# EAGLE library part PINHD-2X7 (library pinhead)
PIN HEADER
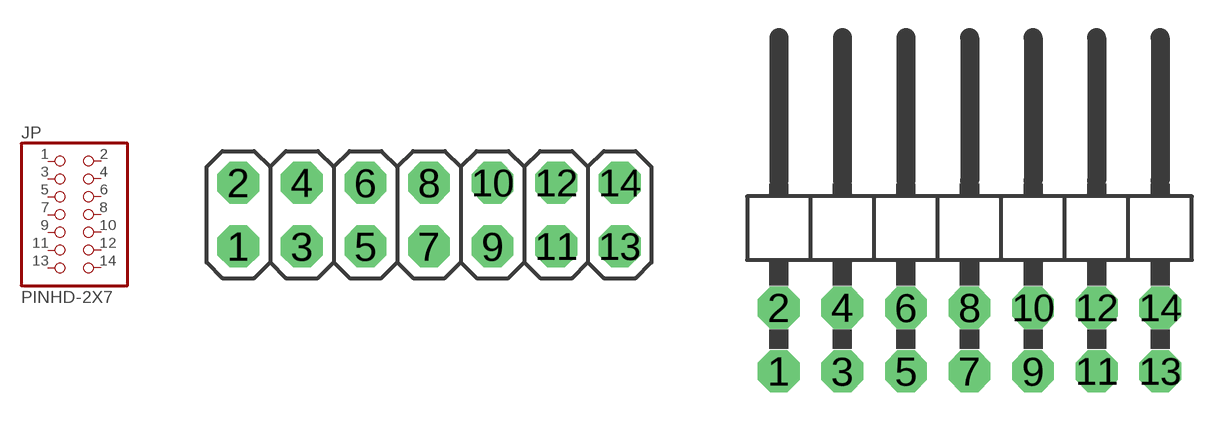
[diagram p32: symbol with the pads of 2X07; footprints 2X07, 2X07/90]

Designator prefix JP

## PINHD-2X7  [2X07]
1  1  pas
2  2  pas
3  3  pas
4  4  pas
5  5  pas
6  6  pas
7  7  pas
8  8  pas
9  9  pas
10  10  pas
11  11  pas
12  12  pas
13  13  pas
14  14  pas

## PINHD-2X7/90  [2X07/90]
Pads as for 2X07

## Footprint 2X07 (pad centres in mm)
PIN HEADER
drill 1.016 pad 1.67 octagon: 1 -7.62,-1.27; 2 -7.62,1.27; 3 -5.08,-1.27; 4 -5.08,1.27; 5 -2.54,-1.27; 6 -2.54,1.27; 7 0,-1.27; 8 0,1.27; 9 2.54,-1.27; 10 2.54,1.27; 11 5.08,-1.27; 12 5.08,1.27; 13 7.62,-1.27; 14 7.62,1.27

## Footprint 2X07/90 (pad centres in mm)
PIN HEADER
drill 1.016 pad 1.67 octagon: 1 -7.62,-6.35; 2 -7.62,-3.81; 3 -5.08,-6.35; 4 -5.08,-3.81; 5 -2.54,-6.35; 6 -2.54,-3.81; 7 0,-6.35; 8 0,-3.81; 9 2.54,-6.35; 10 2.54,-3.81; 11 5.08,-6.35; 12 5.08,-3.81; 13 7.62,-6.35; 14 7.62,-3.81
